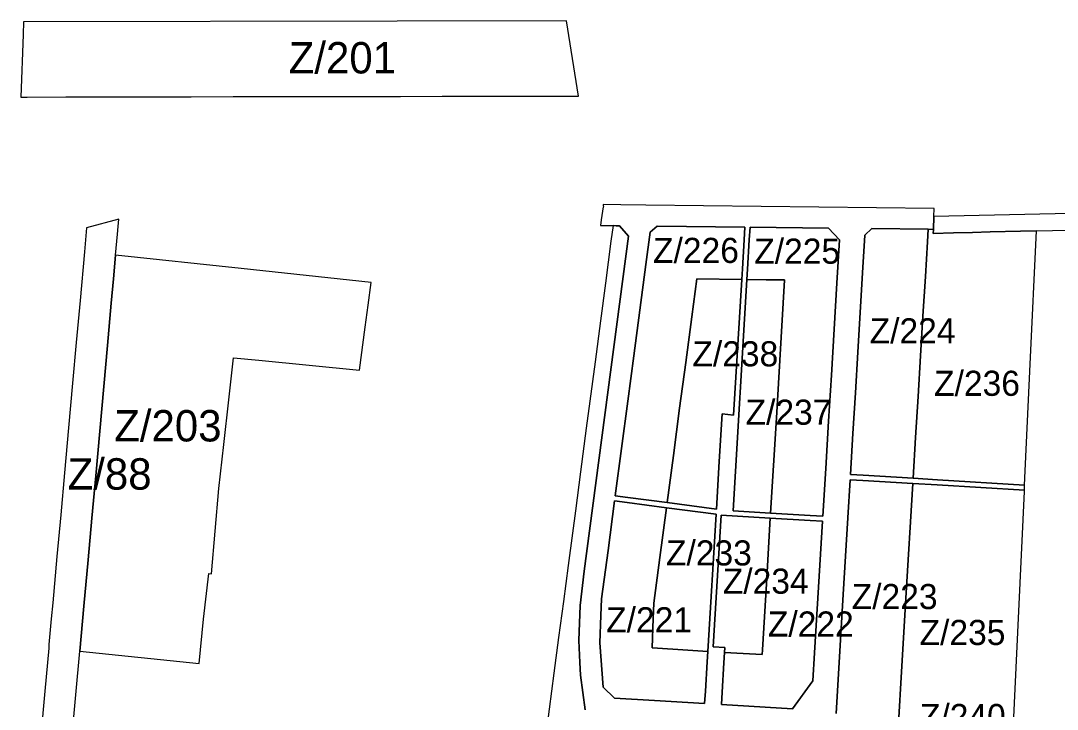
# Model space of a CAD drawing. Extents: x -521939 to -518034, y -1194984 to -1189555.
# Drawn here: x -519696 to -519200.7, y -1191215.8 to -1190886.7 of the extents above; entities that cross this region are included whole.
import ezdxf

# ---------------------------------------------------------------- set-up
doc = ezdxf.new("R2010")
doc.units = 0
for name, color, linetype in [('95420023', 7, 'Continuous'), ('96111023', 7, 'Continuous'), ('96202223', 7, 'Continuous'), ('96202323', 7, 'Continuous')]:
    doc.layers.add(name, color=color, linetype=linetype)

msp = doc.modelspace()

# ---------------------------------------------------------------- linework, layer by layer
at = {"layer": '95420023'}
for points in [[(-519694.59, -1190887.19), (-519694.83, -1190893.33)], [(-519435.15, -1190886.72), (-519516.08, -1190886.87), (-519694.59, -1190887.19)], [(-519429.49, -1190922.71), (-519435.15, -1190886.72)], [(-519694.83, -1190893.33), (-519695.96, -1190923.2)], [(-519695.96, -1190923.2), (-519695.95, -1190923.2)], [(-519695.95, -1190923.2), (-519692.95, -1190923.19)], [(-519692.95, -1190923.19), (-519674.43, -1190923.15)], [(-519674.43, -1190923.15), (-519654.53, -1190923.12)], [(-519654.53, -1190923.12), (-519634.52, -1190923.08)], [(-519634.52, -1190923.08), (-519614.52, -1190923.05)], [(-519614.52, -1190923.05), (-519594.53, -1190923.01)], [(-519594.53, -1190923.01), (-519574.53, -1190922.97)], [(-519574.53, -1190922.97), (-519554.53, -1190922.94)], [(-519554.53, -1190922.94), (-519534.53, -1190922.9)], [(-519534.53, -1190922.9), (-519514.53, -1190922.86)], [(-519514.53, -1190922.86), (-519494.53, -1190922.83)], [(-519494.53, -1190922.83), (-519474.53, -1190922.79)], [(-519474.53, -1190922.79), (-519454.53, -1190922.76)], [(-519454.53, -1190922.76), (-519432.53, -1190922.72)], [(-519432.53, -1190922.72), (-519429.49, -1190922.71)], [(-519259.67, -1190980.24), (-519259.53, -1190976.44), (-519397.29, -1190974.84), (-519409.21, -1190974.7), (-519417.62, -1190974.6), (-519417.66, -1190974.95), (-519417.58, -1190975.61), (-519417.75, -1190975.6), (-519418.57, -1190981.92), (-519418.92, -1190984.59), (-519412.96, -1190984.66)], [(-519649.09, -1190981.52), (-519664.52, -1190985.67)], [(-519649.73, -1190988.71), (-519649.41, -1190985.12), (-519649.09, -1190981.52)], [(-519259.89, -1190986.43), (-519259.67, -1190980.24)], [(-519664.52, -1190985.67), (-519665.04, -1190991.42), (-519665.55, -1190997.17)], [(-519412.96, -1190984.66), (-519413.94, -1190992.07), (-519416.58, -1191012.09), (-519418.96, -1191030.07), (-519421.56, -1191049.69), (-519424.05, -1191068.52), (-519425.76, -1191081.47), (-519428.51, -1191102.27), (-519430.97, -1191120.9), (-519432.39, -1191131.65), (-519434.43, -1191147.07), (-519436.7, -1191164.25), (-519438.99, -1191181.55), (-519441.23, -1191198.47), (-519443.51, -1191215.75), (-519445.75, -1191232.74)], [(-519412.96, -1190984.66), (-519411.43, -1190984.67), (-519409.91, -1190984.69)], [(-519409.91, -1190984.69), (-519411.43, -1190984.67), (-519412.96, -1190984.66)], [(-519409.91, -1190984.69), (-519405.56, -1190989.71)], [(-519405.56, -1190989.71), (-519409.91, -1190984.69)], [(-519350.34, -1190991.38), (-519349.98, -1190985.39), (-519391.87, -1190984.9), (-519395.22, -1190987.84)], [(-519395.22, -1190987.84), (-519391.87, -1190984.9), (-519349.98, -1190985.39)], [(-519349.98, -1190985.39), (-519350.34, -1190991.38), (-519351.18, -1191005.37), (-519351.49, -1191010.37)], [(-519304.76, -1190991.38), (-519309.96, -1190985.85), (-519347.48, -1190985.42), (-519347.84, -1190991.41)], [(-519347.84, -1190991.41), (-519347.48, -1190985.42)], [(-519347.48, -1190985.42), (-519309.96, -1190985.85)], [(-519309.96, -1190985.85), (-519304.76, -1190991.38), (-519306.01, -1191012.14)], [(-519289.31, -1190986.09), (-519292.6, -1190989.16)], [(-519292.6, -1190989.16), (-519289.31, -1190986.09), (-519262.38, -1190986.4), (-519259.89, -1190986.43)], [(-519262.38, -1190986.4), (-519289.31, -1190986.09)], [(-519269.55, -1191105.4), (-519257.89, -1191106.1), (-519216.29, -1191108.61), (-519213.59, -1191050.84), (-519210.6, -1190987.17)], [(-519263.74, -1191008.98), (-519262.74, -1190992.4), (-519262.38, -1190986.4)], [(-519262.38, -1190986.4), (-519262.74, -1190992.4)], [(-519259.89, -1190986.43), (-519262.38, -1190986.4)], [(-519259.96, -1190988.33), (-519259.89, -1190986.43)], [(-519232.69, -1190987.61), (-519241.28, -1190987.85)], [(-519218.24, -1190987.34), (-519232.69, -1190987.61)], [(-519210.6, -1190987.17), (-519218.24, -1190987.34)], [(-519650.63, -1190998.76), (-519649.73, -1190988.71)], [(-519405.56, -1190989.71), (-519426.73, -1191149.73), (-519428.73, -1191166.25), (-519429.31, -1191182.88)], [(-519426.73, -1191149.73), (-519405.56, -1190989.71)], [(-519395.22, -1190987.84), (-519397.25, -1191003.18), (-519400.14, -1191024.99), (-519403.03, -1191046.8), (-519405.91, -1191068.61)], [(-519397.25, -1191003.18), (-519395.22, -1190987.84)], [(-519351.18, -1191005.37), (-519350.34, -1190991.38)], [(-519347.84, -1190991.41), (-519348.68, -1191005.4)], [(-519348.68, -1191005.4), (-519347.84, -1190991.41)], [(-519306.01, -1191012.14), (-519304.76, -1190991.38)], [(-519292.6, -1190989.16), (-519293.69, -1191007.17), (-519294.83, -1191026.14), (-519295.97, -1191045.1)], [(-519295.97, -1191045.1), (-519294.83, -1191026.14), (-519293.69, -1191007.17), (-519292.6, -1190989.16)], [(-519262.74, -1190992.4), (-519263.74, -1191008.98), (-519264.88, -1191027.94), (-519266.03, -1191046.91), (-519267.2, -1191066.37)], [(-519250.24, -1190988.04), (-519259.96, -1190988.33)], [(-519241.28, -1190987.85), (-519250.24, -1190988.04)], [(-519665.55, -1190997.17), (-519667.64, -1191020.37)], [(-519650.63, -1190998.76), (-519651.65, -1191010.05)], [(-519651.65, -1191010.05), (-519650.63, -1190998.76)], [(-519590.6, -1191005.15), (-519650.63, -1190998.76)], [(-519528.51, -1191011.75), (-519590.6, -1191005.15)], [(-519400.14, -1191024.99), (-519397.25, -1191003.18)], [(-519375.36, -1191028.27), (-519372.96, -1191010.12), (-519351.49, -1191010.37), (-519351.18, -1191005.37)], [(-519348.68, -1191005.4), (-519348.98, -1191010.4), (-519339.73, -1191010.51)], [(-519348.98, -1191010.4), (-519348.68, -1191005.4)], [(-519651.65, -1191010.05), (-519652.71, -1191021.78)], [(-519652.71, -1191021.78), (-519651.65, -1191010.05)], [(-519531.36, -1191033.18), (-519529.95, -1191022.61), (-519528.51, -1191011.75)], [(-519351.49, -1191010.37), (-519372.96, -1191010.12), (-519375.36, -1191028.27), (-519378.24, -1191050.08), (-519381.13, -1191071.89), (-519384.11, -1191094.44), (-519387.1, -1191117.04)], [(-519387.1, -1191117.04), (-519363.6, -1191120.15), (-519362.23, -1191097.34), (-519360.86, -1191074.57), (-519355.39, -1191075.29), (-519351.49, -1191010.37)], [(-519351.49, -1191010.37), (-519355.39, -1191075.29), (-519360.86, -1191074.57)], [(-519348.98, -1191010.4), (-519355.64, -1191120.91)], [(-519355.64, -1191120.91), (-519348.98, -1191010.4)], [(-519330.96, -1191010.61), (-519339.73, -1191010.51), (-519348.98, -1191010.4)], [(-519339.73, -1191010.51), (-519330.96, -1191010.61)], [(-519330.96, -1191010.64), (-519332.29, -1191032.6)], [(-519332.29, -1191032.6), (-519330.96, -1191010.64)], [(-519330.96, -1191010.61), (-519330.96, -1191010.64)], [(-519330.96, -1191010.64), (-519330.96, -1191010.61)], [(-519308.65, -1191056.06), (-519307.33, -1191034.1), (-519306.01, -1191012.14)], [(-519306.01, -1191012.14), (-519307.33, -1191034.1), (-519308.65, -1191056.06)], [(-519267.2, -1191066.37), (-519266.03, -1191046.91), (-519264.88, -1191027.94), (-519263.74, -1191008.98)], [(-519667.64, -1191020.37), (-519669.45, -1191040.49)], [(-519652.71, -1191021.78), (-519654.53, -1191041.95)], [(-519654.53, -1191041.95), (-519652.71, -1191021.78)], [(-519405.91, -1191068.61), (-519403.03, -1191046.8), (-519400.14, -1191024.99)], [(-519378.24, -1191050.08), (-519375.36, -1191028.27)], [(-519534.1, -1191053.67), (-519531.36, -1191033.18)], [(-519334.93, -1191076.52), (-519333.61, -1191054.56), (-519332.29, -1191032.6)], [(-519332.29, -1191032.6), (-519333.61, -1191054.56)], [(-519669.45, -1191040.49), (-519671.21, -1191060)], [(-519654.53, -1191041.95), (-519656.29, -1191061.59)], [(-519656.29, -1191061.59), (-519654.53, -1191041.95)], [(-519295.97, -1191045.1), (-519297.14, -1191064.57)], [(-519297.14, -1191064.57), (-519295.97, -1191045.1)], [(-519596.57, -1191067.96), (-519594.32, -1191047.81)], [(-519594.32, -1191047.81), (-519582.27, -1191048.98)], [(-519582.27, -1191048.98), (-519534.1, -1191053.67)], [(-519384.11, -1191094.44), (-519381.13, -1191071.89), (-519378.24, -1191050.08)], [(-519333.61, -1191054.56), (-519334.93, -1191076.52), (-519336.3, -1191099.23), (-519337.67, -1191121.99)], [(-519309.98, -1191078.02), (-519308.65, -1191056.06)], [(-519308.65, -1191056.06), (-519309.98, -1191078.02)], [(-519671.21, -1191060), (-519673.12, -1191081.21)], [(-519656.29, -1191061.59), (-519658.21, -1191082.84)], [(-519658.21, -1191082.84), (-519656.29, -1191061.59)], [(-519297.14, -1191064.57), (-519298.32, -1191084.03)], [(-519298.32, -1191084.03), (-519297.14, -1191064.57)], [(-519268.37, -1191085.84), (-519267.2, -1191066.37)], [(-519267.2, -1191066.37), (-519268.37, -1191085.84)], [(-519598.96, -1191089.31), (-519596.57, -1191067.96)], [(-519405.91, -1191068.61), (-519408.9, -1191091.16), (-519411.89, -1191113.76)], [(-519408.9, -1191091.16), (-519405.91, -1191068.61)], [(-519360.86, -1191074.57), (-519362.23, -1191097.34), (-519363.6, -1191120.15), (-519387.1, -1191117.04)], [(-519336.3, -1191099.23), (-519334.93, -1191076.52)], [(-519673.12, -1191081.21), (-519675.06, -1191102.74)], [(-519318.7, -1191123.13), (-519312.71, -1191123.49), (-519311.34, -1191100.73), (-519309.98, -1191078.02)], [(-519309.98, -1191078.02), (-519311.34, -1191100.73)], [(-519658.21, -1191082.84), (-519660.14, -1191104.26)], [(-519660.14, -1191104.26), (-519658.21, -1191082.84)], [(-519298.32, -1191084.03), (-519299.49, -1191103.6)], [(-519299.49, -1191103.6), (-519298.32, -1191084.03)], [(-519269.55, -1191105.4), (-519268.37, -1191085.84)], [(-519268.37, -1191085.84), (-519269.55, -1191105.4)], [(-519601.29, -1191110.25), (-519598.96, -1191089.31)], [(-519405.94, -1191114.55), (-519411.89, -1191113.76), (-519408.9, -1191091.16)], [(-519387.1, -1191117.04), (-519384.11, -1191094.44)], [(-519355.64, -1191120.91), (-519337.67, -1191121.99), (-519336.3, -1191099.23)], [(-519311.34, -1191100.73), (-519312.71, -1191123.49), (-519318.7, -1191123.13)], [(-519675.06, -1191102.74), (-519676.87, -1191122.79)], [(-519660.14, -1191104.26), (-519661.95, -1191124.38)], [(-519661.95, -1191124.38), (-519660.14, -1191104.26)], [(-519301.84, -1191142.63), (-519300.74, -1191124.36), (-519299.64, -1191106.09), (-519293.65, -1191106.46)], [(-519299.64, -1191106.09), (-519300.74, -1191124.36)], [(-519293.65, -1191106.46), (-519299.64, -1191106.09)], [(-519299.49, -1191103.6), (-519293.5, -1191103.96), (-519269.55, -1191105.4)], [(-519269.55, -1191105.4), (-519293.5, -1191103.96), (-519299.49, -1191103.6)], [(-519269.7, -1191107.9), (-519293.65, -1191106.46)], [(-519293.65, -1191106.46), (-519269.7, -1191107.9)], [(-519258.03, -1191108.6), (-519216.41, -1191111.11), (-519216.29, -1191108.61), (-519257.89, -1191106.1), (-519269.55, -1191105.4)], [(-519603.11, -1191130.62), (-519601.29, -1191110.25)], [(-519269.7, -1191107.9), (-519270.8, -1191126.16), (-519271.9, -1191144.43)], [(-519270.8, -1191126.16), (-519269.7, -1191107.9)], [(-519258.03, -1191108.6), (-519269.7, -1191107.9)], [(-519269.7, -1191107.9), (-519258.03, -1191108.6)], [(-519269, -1191220.09), (-519221.65, -1191222.94), (-519219.11, -1191168.85), (-519216.44, -1191111.73), (-519216.41, -1191111.11)], [(-519216.41, -1191111.11), (-519258.03, -1191108.6)], [(-519390.57, -1191143.26), (-519387.43, -1191119.47), (-519406.26, -1191116.98), (-519412.21, -1191116.19), (-519415.36, -1191139.98), (-519418.4, -1191162.95)], [(-519415.36, -1191139.98), (-519412.21, -1191116.19), (-519406.26, -1191116.98)], [(-519411.89, -1191113.76), (-519405.94, -1191114.55)], [(-519405.94, -1191114.55), (-519387.1, -1191117.04)], [(-519387.1, -1191117.04), (-519405.94, -1191114.55)], [(-519406.26, -1191116.98), (-519387.43, -1191119.47)], [(-519387.43, -1191119.47), (-519390.57, -1191143.26), (-519393.46, -1191165.11), (-519393.76, -1191172.43)], [(-519367.7, -1191188.1), (-519363.75, -1191122.6), (-519387.43, -1191119.47)], [(-519387.43, -1191119.47), (-519363.75, -1191122.6), (-519367.7, -1191188.1), (-519368, -1191193.09)], [(-519337.67, -1191121.99), (-519355.64, -1191120.91)], [(-519676.87, -1191122.79), (-519678.66, -1191142.72)], [(-519661.95, -1191124.38), (-519663.75, -1191144.4)], [(-519663.75, -1191144.4), (-519661.95, -1191124.38)], [(-519361.27, -1191123.02), (-519365.06, -1191185.91)], [(-519365.06, -1191185.91), (-519361.27, -1191123.02), (-519337.82, -1191124.43), (-519318.85, -1191125.58), (-519312.86, -1191125.94), (-519314.75, -1191157.38)], [(-519339.71, -1191155.88), (-519337.82, -1191124.43), (-519361.27, -1191123.02)], [(-519337.82, -1191124.43), (-519339.71, -1191155.88)], [(-519317.45, -1191202.15), (-519316.65, -1191188.82), (-519314.75, -1191157.38), (-519312.86, -1191125.94), (-519318.85, -1191125.58), (-519337.82, -1191124.43)], [(-519337.67, -1191121.99), (-519318.7, -1191123.13)], [(-519318.7, -1191123.13), (-519337.67, -1191121.99)], [(-519300.74, -1191124.36), (-519301.84, -1191142.63), (-519302.94, -1191160.9)], [(-519271.9, -1191144.43), (-519270.8, -1191126.16)], [(-519604.84, -1191151.04), (-519603.11, -1191130.62)], [(-519418.4, -1191162.95), (-519415.36, -1191139.98)], [(-519678.66, -1191142.72), (-519680.66, -1191164.96)], [(-519663.75, -1191144.4), (-519665.75, -1191166.57)], [(-519665.75, -1191166.57), (-519663.75, -1191144.4)], [(-519393.46, -1191165.11), (-519390.57, -1191143.26)], [(-519302.94, -1191160.9), (-519301.84, -1191142.63)], [(-519271.9, -1191144.43), (-519273, -1191162.7)], [(-519273, -1191162.7), (-519271.9, -1191144.43)], [(-519608.58, -1191172.73), (-519606.11, -1191150.9)], [(-519606.11, -1191150.9), (-519604.84, -1191151.04)], [(-519428.73, -1191166.25), (-519426.73, -1191149.73)], [(-519341.6, -1191187.32), (-519339.71, -1191155.88)], [(-519339.71, -1191155.88), (-519341.6, -1191187.32)], [(-519314.75, -1191157.38), (-519316.65, -1191188.82), (-519317.45, -1191202.15)], [(-519302.94, -1191160.9), (-519304.09, -1191179.86), (-519305.23, -1191198.83), (-519306.37, -1191217.84)], [(-519306.37, -1191217.84), (-519305.23, -1191198.83), (-519304.09, -1191179.86), (-519302.94, -1191160.9)], [(-519680.66, -1191164.96), (-519681.35, -1191172.59)], [(-519418.4, -1191162.95), (-519418.72, -1191170.93)], [(-519418.72, -1191170.93), (-519418.4, -1191162.95)], [(-519394.33, -1191186.5), (-519393.76, -1191172.43), (-519393.46, -1191165.11)], [(-519273, -1191162.7), (-519274.14, -1191181.66)], [(-519274.14, -1191181.66), (-519273, -1191162.7)], [(-519665.75, -1191166.57), (-519667.69, -1191188.06)], [(-519667.69, -1191188.06), (-519665.75, -1191166.57)], [(-519429.31, -1191182.88), (-519428.73, -1191166.25)], [(-519681.35, -1191172.59), (-519682.46, -1191184.87)], [(-519610.65, -1191193.91), (-519608.58, -1191172.73)], [(-519418.72, -1191170.93), (-519419.26, -1191184.09), (-519417.68, -1191205.18)], [(-519419.26, -1191184.09), (-519418.72, -1191170.93)], [(-519393.76, -1191172.43), (-519394.33, -1191186.5), (-519391.65, -1191186.66)], [(-519682.46, -1191184.87), (-519682.61, -1191186.53)], [(-519429.31, -1191182.88), (-519428.77, -1191193.5)], [(-519428.77, -1191193.5), (-519429.31, -1191182.88)], [(-519412.25, -1191210.47), (-519417.68, -1191205.18), (-519419.26, -1191184.09)], [(-519274.14, -1191181.66), (-519275.28, -1191200.63), (-519276.43, -1191219.64)], [(-519276.43, -1191219.64), (-519275.28, -1191200.63), (-519274.14, -1191181.66)], [(-519682.61, -1191186.53), (-519684.47, -1191207.19)], [(-519669.56, -1191208.87), (-519667.69, -1191188.06)], [(-519667.69, -1191188.06), (-519610.65, -1191193.91)], [(-519391.65, -1191186.66), (-519394.33, -1191186.5)], [(-519391.65, -1191186.66), (-519379.67, -1191187.38)], [(-519379.67, -1191187.38), (-519391.65, -1191186.66)], [(-519379.67, -1191187.38), (-519367.7, -1191188.1)], [(-519367.7, -1191188.1), (-519379.67, -1191187.38)], [(-519369.2, -1191213.06), (-519368.84, -1191207.07), (-519368, -1191193.09), (-519367.7, -1191188.1)], [(-519365.06, -1191185.91), (-519359.57, -1191186.24)], [(-519359.57, -1191186.24), (-519365.06, -1191185.91)], [(-519317.45, -1191202.15), (-519327.17, -1191215.59), (-519361.21, -1191213.54), (-519360.85, -1191207.55), (-519360.01, -1191193.57), (-519359.71, -1191188.58)], [(-519359.71, -1191188.58), (-519360.01, -1191193.57)], [(-519359.57, -1191186.24), (-519359.71, -1191188.58)], [(-519359.71, -1191188.58), (-519359.57, -1191186.24)], [(-519359.71, -1191188.58), (-519350.73, -1191189.12), (-519341.74, -1191189.67)], [(-519350.73, -1191189.12), (-519359.71, -1191188.58)], [(-519341.74, -1191189.67), (-519350.73, -1191189.12)], [(-519341.74, -1191189.67), (-519341.6, -1191187.32)], [(-519341.6, -1191187.32), (-519341.74, -1191189.67)], [(-519428.77, -1191193.5), (-519428.47, -1191199.49)], [(-519428.47, -1191199.49), (-519428.77, -1191193.5)], [(-519368, -1191193.09), (-519368.84, -1191207.07)], [(-519360.01, -1191193.57), (-519360.85, -1191207.55), (-519361.21, -1191213.54), (-519327.17, -1191215.59)], [(-519428.47, -1191199.49), (-519426.21, -1191215.98)], [(-519426.21, -1191215.98), (-519428.47, -1191199.49)], [(-519417.68, -1191205.18), (-519412.25, -1191210.47), (-519393.15, -1191211.62)], [(-519327.17, -1191215.59), (-519317.45, -1191202.15)], [(-519684.47, -1191207.19), (-519686.37, -1191228.29)], [(-519671.47, -1191230.02), (-519669.56, -1191208.87)], [(-519393.15, -1191211.62), (-519412.25, -1191210.47)], [(-519368.84, -1191207.07), (-519369.2, -1191213.06)], [(-519393.15, -1191211.62), (-519369.2, -1191213.06)], [(-519369.2, -1191213.06), (-519393.15, -1191211.62)]]:
    msp.add_lwpolyline(points, dxfattribs=at)
at = {"layer": '96111023'}
for points in [[(-519107.55, -1190976.87), (-519259.67, -1190980.24), (-519259.89, -1190986.43)], [(-519259.89, -1190986.43), (-519259.96, -1190988.33)], [(-519241.28, -1190987.85), (-519232.69, -1190987.61), (-519218.24, -1190987.34), (-519210.6, -1190987.17)], [(-519210.6, -1190987.17), (-519202.99, -1190986.99), (-519195.39, -1190986.84)], [(-519259.96, -1190988.33), (-519250.24, -1190988.04)], [(-519250.24, -1190988.04), (-519241.28, -1190987.85)]]:
    msp.add_lwpolyline(points, dxfattribs=at)
at = {"layer": '96202223'}
for points in [[(-519107.55, -1190976.87), (-519259.67, -1190980.24)], [(-519259.67, -1190980.24), (-519259.89, -1190986.43)], [(-519412.96, -1190984.66), (-519413.94, -1190992.07), (-519416.58, -1191012.09), (-519418.96, -1191030.07), (-519421.56, -1191049.69), (-519424.05, -1191068.52), (-519425.76, -1191081.47), (-519428.51, -1191102.27), (-519430.97, -1191120.9), (-519432.39, -1191131.65), (-519434.43, -1191147.07), (-519436.7, -1191164.25), (-519438.99, -1191181.55), (-519441.23, -1191198.47), (-519443.51, -1191215.75), (-519445.75, -1191232.74)], [(-519409.91, -1190984.69), (-519411.43, -1190984.67), (-519412.96, -1190984.66)], [(-519405.56, -1190989.71), (-519409.91, -1190984.69)], [(-519259.89, -1190986.43), (-519259.96, -1190988.33)], [(-519241.28, -1190987.85), (-519232.69, -1190987.61)], [(-519232.69, -1190987.61), (-519218.24, -1190987.34)], [(-519218.24, -1190987.34), (-519210.6, -1190987.17)], [(-519210.6, -1190987.17), (-519202.99, -1190986.99), (-519195.39, -1190986.84)], [(-519426.73, -1191149.73), (-519405.56, -1190989.71)], [(-519259.96, -1190988.33), (-519250.24, -1190988.04)], [(-519250.24, -1190988.04), (-519241.28, -1190987.85)], [(-519429.31, -1191182.88), (-519428.73, -1191166.25), (-519426.73, -1191149.73)], [(-519428.77, -1191193.5), (-519429.31, -1191182.88)], [(-519428.47, -1191199.49), (-519428.77, -1191193.5)], [(-519426.21, -1191215.98), (-519428.47, -1191199.49)]]:
    msp.add_lwpolyline(points, dxfattribs=at)
at = {"layer": '96202323'}
for points in [[(-519259.67, -1190980.24), (-519259.53, -1190976.44), (-519397.29, -1190974.84), (-519409.21, -1190974.7), (-519417.62, -1190974.6), (-519417.66, -1190974.95), (-519417.58, -1190975.61), (-519417.75, -1190975.6), (-519418.57, -1190981.92), (-519418.92, -1190984.59), (-519412.96, -1190984.66)], [(-519259.89, -1190986.43), (-519259.67, -1190980.24)], [(-519412.96, -1190984.66), (-519411.43, -1190984.67), (-519409.91, -1190984.69)], [(-519409.91, -1190984.69), (-519405.56, -1190989.71)], [(-519395.22, -1190987.84), (-519391.87, -1190984.9), (-519349.98, -1190985.39)], [(-519349.98, -1190985.39), (-519350.34, -1190991.38)], [(-519347.84, -1190991.41), (-519347.48, -1190985.42)], [(-519347.48, -1190985.42), (-519309.96, -1190985.85)], [(-519309.96, -1190985.85), (-519304.76, -1190991.38)], [(-519292.6, -1190989.16), (-519289.31, -1190986.09)], [(-519289.31, -1190986.09), (-519262.38, -1190986.4)], [(-519262.38, -1190986.4), (-519259.89, -1190986.43)], [(-519405.56, -1190989.71), (-519426.73, -1191149.73), (-519428.73, -1191166.25), (-519429.31, -1191182.88)], [(-519397.25, -1191003.18), (-519395.22, -1190987.84)], [(-519350.34, -1190991.38), (-519351.18, -1191005.37)], [(-519348.68, -1191005.4), (-519347.84, -1190991.41)], [(-519304.76, -1190991.38), (-519306.01, -1191012.14)], [(-519293.69, -1191007.17), (-519292.6, -1190989.16)], [(-519400.14, -1191024.99), (-519397.25, -1191003.18)], [(-519351.18, -1191005.37), (-519351.49, -1191010.37)], [(-519348.98, -1191010.4), (-519348.68, -1191005.4)], [(-519295.97, -1191045.1), (-519294.83, -1191026.14), (-519293.69, -1191007.17)], [(-519351.49, -1191010.37), (-519355.39, -1191075.29), (-519360.86, -1191074.57)], [(-519355.64, -1191120.91), (-519348.98, -1191010.4)], [(-519306.01, -1191012.14), (-519307.33, -1191034.1)], [(-519405.91, -1191068.61), (-519403.03, -1191046.8), (-519400.14, -1191024.99)], [(-519307.33, -1191034.1), (-519308.65, -1191056.06)], [(-519297.14, -1191064.57), (-519295.97, -1191045.1)], [(-519308.65, -1191056.06), (-519309.98, -1191078.02)], [(-519298.32, -1191084.03), (-519297.14, -1191064.57)], [(-519411.89, -1191113.76), (-519408.9, -1191091.16), (-519405.91, -1191068.61)], [(-519360.86, -1191074.57), (-519362.23, -1191097.34)], [(-519309.98, -1191078.02), (-519311.34, -1191100.73), (-519312.71, -1191123.49)], [(-519299.49, -1191103.6), (-519298.32, -1191084.03)], [(-519362.23, -1191097.34), (-519363.6, -1191120.15)], [(-519300.74, -1191124.36), (-519299.64, -1191106.09)], [(-519299.64, -1191106.09), (-519293.65, -1191106.46)], [(-519269.55, -1191105.4), (-519293.5, -1191103.96), (-519299.49, -1191103.6)], [(-519293.65, -1191106.46), (-519269.7, -1191107.9)], [(-519216.29, -1191108.61), (-519257.89, -1191106.1), (-519269.55, -1191105.4)], [(-519269.7, -1191107.9), (-519258.03, -1191108.6)], [(-519258.03, -1191108.6), (-519216.41, -1191111.11)], [(-519216.41, -1191111.11), (-519216.29, -1191108.61)], [(-519415.36, -1191139.98), (-519412.21, -1191116.19), (-519406.26, -1191116.98)], [(-519405.94, -1191114.55), (-519411.89, -1191113.76)], [(-519387.1, -1191117.04), (-519405.94, -1191114.55)], [(-519406.26, -1191116.98), (-519387.43, -1191119.47)], [(-519387.43, -1191119.47), (-519363.75, -1191122.6), (-519367.7, -1191188.1), (-519368, -1191193.09)], [(-519363.6, -1191120.15), (-519387.1, -1191117.04)], [(-519337.67, -1191121.99), (-519355.64, -1191120.91)], [(-519365.06, -1191185.91), (-519361.27, -1191123.02)], [(-519361.27, -1191123.02), (-519337.82, -1191124.43)], [(-519337.82, -1191124.43), (-519318.85, -1191125.58)], [(-519318.7, -1191123.13), (-519337.67, -1191121.99)], [(-519318.85, -1191125.58), (-519312.86, -1191125.94)], [(-519312.71, -1191123.49), (-519318.7, -1191123.13)], [(-519312.86, -1191125.94), (-519314.75, -1191157.38)], [(-519301.84, -1191142.63), (-519300.74, -1191124.36)], [(-519418.4, -1191162.95), (-519415.36, -1191139.98)], [(-519302.94, -1191160.9), (-519301.84, -1191142.63)], [(-519314.75, -1191157.38), (-519316.65, -1191188.82), (-519317.45, -1191202.15)], [(-519304.09, -1191179.86), (-519302.94, -1191160.9)], [(-519418.72, -1191170.93), (-519418.4, -1191162.95)], [(-519419.26, -1191184.09), (-519418.72, -1191170.93)], [(-519306.37, -1191217.84), (-519305.23, -1191198.83), (-519304.09, -1191179.86)], [(-519429.31, -1191182.88), (-519428.77, -1191193.5)], [(-519412.25, -1191210.47), (-519417.68, -1191205.18), (-519419.26, -1191184.09)], [(-519359.57, -1191186.24), (-519365.06, -1191185.91)], [(-519360.01, -1191193.57), (-519359.71, -1191188.58)], [(-519359.71, -1191188.58), (-519359.57, -1191186.24)], [(-519428.77, -1191193.5), (-519428.47, -1191199.49)], [(-519368, -1191193.09), (-519368.84, -1191207.07)], [(-519361.21, -1191213.54), (-519360.85, -1191207.55), (-519360.01, -1191193.57)], [(-519428.47, -1191199.49), (-519426.21, -1191215.98)], [(-519317.45, -1191202.15), (-519327.17, -1191215.59)], [(-519393.15, -1191211.62), (-519412.25, -1191210.47)], [(-519368.84, -1191207.07), (-519369.2, -1191213.06)], [(-519369.2, -1191213.06), (-519393.15, -1191211.62)], [(-519327.17, -1191215.59), (-519361.21, -1191213.54)]]:
    msp.add_lwpolyline(points, dxfattribs=at)

# ---------------------------------------------------------------- texts
at = {"layer": '95420023'}
for s, height, rotation, p in [('Z/201', 15, 360, (-519567.93, -1190911.92)), ('Z/225', 12, 360, (-519345.5, -1191002.84)), ('Z/224', 12, 360, (-519290.35, -1191040.93)), ('Z/238', 12, 360, (-519375.04, -1191051.9)), ('Z/236', 12, 360, (-519259.57, -1191065.99)), ('Z/237', 12, 360, (-519349.65, -1191079.8)), ('Z/203', 15, 360, (-519651.31, -1191087.79)), ('Z/88', 15, 0, (-519673.58, -1191110.82)), ('Z/233', 12, 360, (-519387.67, -1191147.06)), ('Z/234', 12, 0, (-519360.52, -1191160.55)), ('Z/223', 12, 0, (-519298.94, -1191167.92)), ('Z/221', 12, 360, (-519416.26, -1191179.02)), ('Z/222', 12, 0, (-519338.99, -1191181.04)), ('Z/235', 12, 0, (-519266.51, -1191185.07)), ('Z/240', 12, 360, (-519266.35, -1191225.26))]:
    msp.add_text(s, height=height, rotation=rotation, dxfattribs=at).set_placement(p)
msp.add_text('Z/226', height=12, dxfattribs=at).set_placement((-519393.85, -1191002.48))

doc.saveas('drawing.dxf')
